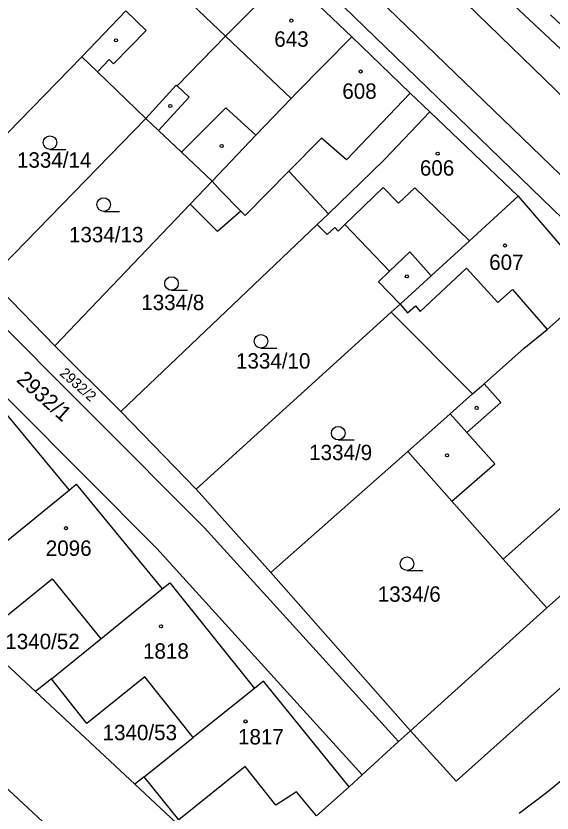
# Model space of a CAD drawing. Extents: x -779596 to -776743, y -1030330 to -1024513.
# Drawn here: x -778842.6 to -778783.4, y -1030205.8 to -1030117.8 of the extents above; entities that cross this region are included whole.
import ezdxf

# ---------------------------------------------------------------- set-up
doc = ezdxf.new("R2010")
doc.units = 0
for name, color, linetype in [('hranice parcel', 7, 'Continuous'), ('hranice vnitřní', 7, 'Continuous'), ('kultura', 7, 'Continuous'), ('č_pacel stav_', 7, 'Continuous'), ('č_parcel poz_', 7, 'Continuous')]:
    doc.layers.add(name, color=color, linetype=linetype)

msp = doc.modelspace()

# ---------------------------------------------------------------- linework, layer by layer
at = {"layer": 'hranice parcel'}
for points in [[(-778865.3, -1030043.83), (-778766.38, -1030136.5)], [(-778829.42, -1030094.44), (-778776.49, -1030145.76)], [(-778819.45, -1030120), (-778812.73, -1030113.2)], [(-778812.73, -1030113.2), (-778805.52, -1030120.09)], [(-778830.45, -1030117.23), (-778835.3, -1030122.28)], [(-778783.58, -1030117.67), (-778775.48, -1030125.29)], [(-778824.78, -1030125.49), (-778819.45, -1030120)], [(-778805.52, -1030120.09), (-778811.66, -1030126.31)], [(-778805.52, -1030120.09), (-778799.06, -1030126.3)], [(-778835.3, -1030122.28), (-778846.29, -1030133.53)], [(-778835.3, -1030122.28), (-778833.57, -1030123.94)], [(-778833.57, -1030123.94), (-778828.25, -1030129.1)], [(-778828.25, -1030129.1), (-778824.89, -1030125.42)], [(-778824.89, -1030125.42), (-778824.78, -1030125.49)], [(-778811.66, -1030126.31), (-778812.22, -1030126.88)], [(-778799.06, -1030126.3), (-778796.9, -1030128.38)], [(-778812.22, -1030126.88), (-778816.11, -1030130.96)], [(-778796.9, -1030128.38), (-778801.87, -1030133.6)], [(-778787.14, -1030137.68), (-778796.9, -1030128.38)], [(-778828.25, -1030129.1), (-778845.5, -1030146.8)], [(-778826.85, -1030130.43), (-778828.25, -1030129.1)], [(-778824.31, -1030132.84), (-778826.85, -1030130.43)], [(-778816.11, -1030130.96), (-778820.94, -1030136.03)], [(-778824.31, -1030132.84), (-778820.94, -1030136.03)], [(-778801.87, -1030133.6), (-778803.31, -1030134.99)], [(-778817.75, -1030139.35), (-778817.27, -1030139.83), (-778812.47, -1030134.91)], [(-778808.1, -1030139.63), (-778812.47, -1030134.91)], [(-778803.31, -1030134.99), (-778808.1, -1030139.63)], [(-778820.94, -1030136.03), (-778823.36, -1030138.58)], [(-778866.79, -1030136.67), (-778827.03, -1030176.61)], [(-778792.52, -1030142.6), (-778787.14, -1030137.68)], [(-778787.14, -1030137.68), (-778778.57, -1030147.67)], [(-778823.36, -1030138.58), (-778838.3, -1030154.2)], [(-778823.36, -1030138.58), (-778820.32, -1030141.57)], [(-778817.75, -1030139.35), (-778820.32, -1030141.57)], [(-778808.1, -1030139.63), (-778809.32, -1030140.81)], [(-778831, -1030161.45), (-778809.32, -1030140.81)], [(-778809.32, -1030140.81), (-778808.23, -1030141.93)], [(-778808.23, -1030141.93), (-778807.39, -1030141.15)], [(-778807.39, -1030141.15), (-778807.02, -1030141.54)], [(-778807.02, -1030141.54), (-778806.27, -1030140.8)], [(-778806.27, -1030140.8), (-778801.34, -1030145.96)], [(-778792.52, -1030142.6), (-778796.74, -1030146.47)], [(-778801.34, -1030145.96), (-778802.57, -1030147.14)], [(-778838.3, -1030154.2), (-778845.5, -1030146.8)], [(-778796.74, -1030146.47), (-778800.19, -1030149.63)], [(-778802.57, -1030147.14), (-778800.19, -1030149.63)], [(-778783.95, -1030152.42), (-778778.57, -1030147.67)], [(-778821.8, -1030174.27), (-778846.41, -1030149.6)], [(-778800.19, -1030149.63), (-778801.15, -1030150.51)], [(-778822.7, -1030170.05), (-778801.15, -1030150.51)], [(-778801.15, -1030150.51), (-778792.19, -1030159.53)], [(-778786.49, -1030154.46), (-778783.95, -1030152.42)], [(-778831, -1030161.45), (-778838.3, -1030154.2)], [(-778790.92, -1030158.4), (-778786.49, -1030154.46)], [(-778846.29, -1030158.65), (-778836.71, -1030170.14)], [(-778792.19, -1030159.53), (-778790.92, -1030158.4)], [(-778794.64, -1030161.71), (-778792.19, -1030159.53)], [(-778822.7, -1030170.05), (-778831, -1030161.45)], [(-778799.33, -1030165.88), (-778794.64, -1030161.71)], [(-778814.45, -1030179.24), (-778799.33, -1030165.88)], [(-778799.33, -1030165.88), (-778794.48, -1030171.37)], [(-778836.71, -1030170.14), (-778835.94, -1030169.51)], [(-778835.94, -1030169.51), (-778826.45, -1030181.07)], [(-778843.47, -1030175.69), (-778836.71, -1030170.14)], [(-778814.45, -1030179.24), (-778822.7, -1030170.05)], [(-778794.48, -1030171.37), (-778788.8, -1030177.79)], [(-778783.98, -1030183.15), (-778771.21, -1030171.83)], [(-778800.35, -1030197.9), (-778821.8, -1030174.27)], [(-778827.03, -1030176.61), (-778804.38, -1030201.6)], [(-778766.2, -1030177.43), (-778794, -1030202.3)], [(-778788.8, -1030177.79), (-778783.98, -1030183.15)], [(-778799.02, -1030196.73), (-778814.45, -1030179.24)], [(-778845.09, -1030185.21), (-778838.6, -1030179.95)], [(-778838.6, -1030179.95), (-778833.23, -1030186.57)], [(-778833.23, -1030186.57), (-778826.45, -1030181.07)], [(-778826.45, -1030181.07), (-778825.6, -1030180.38)], [(-778825.6, -1030180.38), (-778816.26, -1030192.05)], [(-778840.42, -1030192.4), (-778851.38, -1030182.18)], [(-778799.02, -1030196.73), (-778783.98, -1030183.15)], [(-778838.67, -1030190.98), (-778833.23, -1030186.57)], [(-778828.36, -1030190.79), (-778834.76, -1030195.92)], [(-778823.01, -1030197.46), (-778828.36, -1030190.79)], [(-778838.67, -1030190.98), (-778840.42, -1030192.4)], [(-778834.76, -1030195.92), (-778838.67, -1030190.98)], [(-778815.25, -1030191.24), (-778816.26, -1030192.05)], [(-778805.82, -1030202.92), (-778815.25, -1030191.24)], [(-778829.45, -1030202.63), (-778840.42, -1030192.4)], [(-778816.26, -1030192.05), (-778823.01, -1030197.46)], [(-778800.35, -1030197.9), (-778799.02, -1030196.73)], [(-778794, -1030202.3), (-778799.02, -1030196.73)], [(-778828.44, -1030201.82), (-778823.01, -1030197.46)], [(-778804.38, -1030201.6), (-778800.35, -1030197.9)], [(-778847.19, -1030199.74), (-778826.7, -1030218.83)], [(-778779.4, -1030199.81), (-778784.03, -1030203.57)], [(-778817.3, -1030200.68), (-778824.62, -1030206.57)], [(-778813.89, -1030204.93), (-778817.3, -1030200.68)], [(-778828.44, -1030201.82), (-778829.45, -1030202.63)], [(-778824.62, -1030206.57), (-778828.44, -1030201.82)], [(-778805.82, -1030202.92), (-778804.38, -1030201.6)], [(-778829.45, -1030202.63), (-778819.22, -1030212.18)], [(-778805.82, -1030202.92), (-778809.41, -1030206.11)], [(-778811.62, -1030203.46), (-778813.89, -1030204.93)], [(-778809.41, -1030206.11), (-778811.62, -1030203.46)], [(-778784.03, -1030203.57), (-778787.04, -1030205.87)]]:
    msp.add_lwpolyline(points, dxfattribs=at)
at = {"layer": 'hranice vnitřní'}
for points in [[(-778864.84, -1030046.48), (-778769.35, -1030139.23)], [(-778855.59, -1030064.7), (-778774.03, -1030143.52)], [(-778819.45, -1030120), (-778823.89, -1030115.76)], [(-778830.45, -1030117.23), (-778828.21, -1030119.39)], [(-778828.21, -1030119.39), (-778831.8, -1030123.06)], [(-778819.45, -1030120), (-778812.22, -1030126.88)], [(-778832.28, -1030122.6), (-778833.57, -1030123.94)], [(-778831.8, -1030123.06), (-778832.28, -1030122.6)], [(-778824.78, -1030125.49), (-778823.48, -1030126.74)], [(-778799.06, -1030126.3), (-778806.08, -1030133.66)], [(-778823.48, -1030126.74), (-778826.85, -1030130.43)], [(-778819.41, -1030127.94), (-778824.31, -1030132.84)], [(-778816.11, -1030130.96), (-778819.41, -1030127.94)], [(-778812.47, -1030134.91), (-778808.85, -1030131.28)], [(-778806.08, -1030133.66), (-778808.85, -1030131.28)], [(-778820.05, -1030137.04), (-778820.94, -1030136.03)], [(-778820.05, -1030137.04), (-778817.75, -1030139.35)], [(-778802.06, -1030136.71), (-778806.27, -1030140.8)], [(-778800.35, -1030138.47), (-778802.06, -1030136.71)], [(-778798.56, -1030136.78), (-778800.35, -1030138.47)], [(-778798.56, -1030136.78), (-778792.52, -1030142.6)], [(-778801.34, -1030145.96), (-778799.11, -1030143.84)], [(-778799.11, -1030143.84), (-778796.74, -1030146.47)], [(-778797.97, -1030150.41), (-778792.85, -1030145.63)], [(-778792.85, -1030145.63), (-778789.39, -1030149.44)], [(-778789.39, -1030149.44), (-778787.79, -1030147.99)], [(-778787.79, -1030147.99), (-778783.95, -1030152.42)], [(-778800.19, -1030149.63), (-778799.38, -1030150.57)], [(-778799.38, -1030150.57), (-778798.49, -1030149.81)], [(-778798.49, -1030149.81), (-778797.97, -1030150.41)], [(-778789.08, -1030160.47), (-778790.92, -1030158.4)], [(-778792.8, -1030163.78), (-778789.08, -1030160.47)], [(-778792.8, -1030163.78), (-778794.64, -1030161.71)], [(-778789.73, -1030167.24), (-778792.8, -1030163.78)], [(-778775.99, -1030166.39), (-778788.8, -1030177.79)], [(-778794.48, -1030171.37), (-778789.73, -1030167.24)]]:
    msp.add_lwpolyline(points, dxfattribs=at)
at = {"layer": 'kultura'}
for points in [[(-778838.83, -1030132.52), (-778837.08, -1030132.52)], [(-778832.9, -1030139.36), (-778831.15, -1030139.36)], [(-778825.41, -1030148.08), (-778823.66, -1030148.08)], [(-778815.54, -1030154.46), (-778813.79, -1030154.46)], [(-778807.01, -1030164.61), (-778805.26, -1030164.61)], [(-778799.42, -1030179.03), (-778797.67, -1030179.03)]]:
    msp.add_lwpolyline(points, dxfattribs=at)
for centre, radius in [((-778812.19, -1030118.29), 0.175), ((-778831.54, -1030120.48), 0.175), ((-778804.54, -1030123.92), 0.175), ((-778825.55, -1030127.73), 0.175), ((-778838.83, -1030131.77), 0.75), ((-778819.87, -1030132.15), 0.175), ((-778796.03, -1030133), 0.175), ((-778832.9, -1030138.61), 0.75), ((-778788.6, -1030143.13), 0.175), ((-778825.41, -1030147.33), 0.75), ((-778799.44, -1030146.54), 0.175), ((-778815.54, -1030153.71), 0.75), ((-778791.73, -1030161.07), 0.175), ((-778807.01, -1030163.86), 0.75), ((-778795, -1030166.3), 0.175), ((-778837.06, -1030174.35), 0.175), ((-778799.42, -1030178.28), 0.75), ((-778826.57, -1030185.19), 0.175), ((-778817.25, -1030195.7), 0.175)]:
    msp.add_circle(centre, radius, dxfattribs=at)

# ---------------------------------------------------------------- texts
at = {"layer": 'č_pacel stav_'}
for s, p in [('643', (-778814.07, -1030121.18)), ('608', (-778806.56, -1030126.93)), ('606', (-778798, -1030135.42)), ('607', (-778790.35, -1030145.83)), ('2096', (-778839.29, -1030177.41)), ('1818', (-778828.56, -1030188.77)), ('1817', (-778818.07, -1030198.24))]:
    msp.add_text(s, height=1.7, dxfattribs=at).set_placement(p)
at = {"layer": 'č_parcel poz_'}
for s, p in [('1334/14', (-778842.47, -1030134.54)), ('1334/13', (-778836.73, -1030142.78)), ('1334/8', (-778828.75, -1030150.27)), ('1334/10', (-778818.3, -1030156.73)), ('1334/9', (-778810.22, -1030166.84)), ('1334/6', (-778802.65, -1030182.48)), ('1340/52', (-778843.76, -1030187.71)), ('1340/53', (-778833.02, -1030197.77))]:
    msp.add_text(s, height=1.7, dxfattribs=at).set_placement(p)
for s, height, rotation, p in [('2932/1', 1.7, 318.50253, (-778842.633, -1030158.091)), ('2932/2', 1.14, 318.70254, (-778837.839, -1030157.378))]:
    msp.add_text(s, height=height, rotation=rotation, dxfattribs=at).set_placement(p)

doc.saveas('drawing.dxf')
